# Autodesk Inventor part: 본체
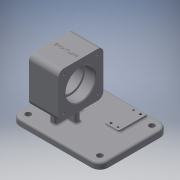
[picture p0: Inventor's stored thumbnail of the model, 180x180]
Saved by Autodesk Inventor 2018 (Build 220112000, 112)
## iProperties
Created: 2019-09
Part Number: 본체
Material: 알루미늄 6061
Document SubType Name: Modeling
Designer: mduedu
Density: 2.71 g/cm^3
Appearance: 기본값
Mass: 636.364 g
Surface Area: 520.125 cm^2
Volume: 234.821 cm^3
Author: mduedu
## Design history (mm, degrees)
sketch "스케치1"
  geometry: L1 (42, -62)-(-84, -62); L2 (-84, -62)-(-84, 36); L3 (-84, 36)-(42, 36); L4 (42, 36)-(42, -62); 1 further point
  constraints: 8 end point, 2 parallel, 1 horizontal, 1 perpendicular
  dimensions: "d0" = 36 distance from line of L3 point (0, 0); "d1" = 98 distance of L1.end L2.end; "d2" = 42 distance from line of L4 point (0, 0); "d3" = 126 distance of L2.end L3.end
extrude "돌출1" new body sketch "스케치1" distance "d4" = 9; taper "d5" = 0 deg
sketch "스케치2"
  geometry: L1 (0, -62)-(0, 36) reference; L2 (27, -32)-(91, -32); L3 (91, -32)-(91, 32); L4 (91, 32)-(27, 32); L5 (27, 32)-(27, -32); L6 (27, -32)-(91, 32); L7 (91, -32)-(27, 32); 3 further points
  constraints: 12 end point, 3 midpoint, 2 parallel, 1 horizontal, 1 horizontal alignment, 1 perpendicular
  dimensions: "d87" = 64 distance of L4.end L3.end; "d88" = 64 distance of L3.end L2.end; "d89" = 59 distance from line of point (59, 0) L1
extrude "돌출2" join sketch "스케치2" stored distance "d8" = 42; taper "d9" = 0 deg
sketch "스케치3"
  geometry: L1 (-17, 4)-(17, 4); L2 (17, 4)-(17, -4); L3 (17, -4)-(-17, -4); L4 (-17, -4)-(-17, 4); L5 (-4, 20)-(4, 20); L6 (4, 20)-(4, -20); L7 (4, -20)-(-4, -20); L8 (-4, -20)-(-4, 20); 5 further points
  constraints: 16 end point, 4 midpoint, 4 parallel, 2 horizontal, 2 horizontal alignment, 2 perpendicular, 2 vertical alignment
  dimensions: "d10" = 8 distance of L5.start L5.end; "d12" = 8 distance of L1.end L2.end; "d13" = 34 distance of L2.end L3.end; "d14" = 40 distance of L5.end L6.end
extrude "돌출3" join sketch "스케치3" stored distance "d15" = 42; taper "d16" = 0 deg
sketch "스케치4"
  geometry: L1 (-32, 91)-(-32, 27) reference; L2 (32, 91)-(-32, 91) reference; L3 (32, 27)-(32, 91) reference; L4 (-32, 27)-(32, 27) reference; C1 r 21 at (0, 59); 3 further points
  constraints: 2 midpoint, 1 centre point, 1 horizontal alignment, 1 vertical alignment
  dimensions: "d17" = 42 diameter of C1
extrude "돌출4" cut sketch "스케치4" distance "d18" = 15; taper "d19" = 0 deg
hole "구멍1" diameter "d22" = 36; stored, may be unused: countersink angle "d26" = 90 deg, drill point angle "d28" = 118 deg; dims "d20" = 10, "d21" = 10, "d23" = 6, "d24" = 4, "d25" = 2, "d27" = 8
fillet "모깎기1" dims "d29" = 0.3
chamfer "모따기1" distance "d30" = 1; stored, may be unused: second distance "d31" = 2, angle "d32" = 45 deg
fillet "모깎기9" dims "d90" = 8
sketch "스케치11"
  geometry: L1 (-24, 27)-(24, 27) reference; L2 (32, 35)-(32, 83) reference; L3 (24, 91)-(-24, 91) reference; L4 (-32, 83)-(-32, 35) reference; C1 r 22 at (0, 59) reference; A1 r 8 centre (-24, 35) between (-32, 35) and (-24, 27) reference; A2 r 8 centre (24, 35) between (24, 27) and (32, 35) reference; A3 r 8 centre (24, 83) between (32, 83) and (24, 91) reference; A4 r 8 centre (-24, 83) between (-24, 91) and (-32, 83) reference; 5 further points
  constraints: 4 coincident
hole "구멍6" sketch "스케치11" at (-24, 83), (24, 83), (24, 35), (-24, 35) diameter "d91" = 3.242; stored, may be unused: countersink angle "d95" = 90 deg, drill point angle "d97" = 118 deg; dims "d92" = 8, "d93" = 4, "d94" = 2, "d96" = 10
fillet "모깎기2" dims "d44" = 12
sketch "스케치6"
  geometry: L1 (-42, 50)-(-42, -24) reference; L2 (-30, -36)-(72, -36) reference; L3 (84, -24)-(84, 50) reference; L4 (72, 62)-(-30, 62) reference; L5 (17, 4)-(17, -4) reference; L6 (17, -4)-(4, -4) reference; L7 (4, -4)-(4, -20) reference; L8 (4, -20)-(-4, -20) reference; L9 (-4, -20)-(-4, -4) reference; L10 (-4, -4)-(-17, -4) reference; L11 (-17, -4)-(-17, 4) reference; L12 (-17, 4)-(-4, 4) reference; L13 (-4, 4)-(-4, 20) reference; L14 (-4, 20)-(4, 20) reference; L15 (4, 20)-(4, 4) reference; L16 (4, 4)-(17, 4) reference; A1 r 12 centre (-30, 50) between (-30, 62) and (-42, 50) reference; A2 r 12 centre (-30, -24) between (-42, -24) and (-30, -36) reference; A3 r 12 centre (72, -24) between (72, -36) and (84, -24) reference; A4 r 12 centre (72, 50) between (84, 50) and (72, 62) reference; 5 further points
  constraints: 4 coincident
hole "구멍3" sketch "스케치6" at (-30, 50), (72, 50), (72, -24), (-30, -24) diameter "d45" = 8; stored, may be unused: countersink angle "d49" = 90 deg, drill point angle "d51" = 118 deg; dims "d46" = 8, "d47" = 4, "d48" = 2, "d50" = 10
sketch "스케치7"
  geometry: L1 (38, 57)-(58, 57); L2 (58, 57)-(58, 17); L3 (58, 17)-(38, 17); L4 (38, 17)-(38, 57); L5 (72, 62)-(-30, 62) reference; 3 further points
  constraints: 8 end point, 2 midpoint, 2 parallel, 1 horizontal, 1 perpendicular
  dimensions: "d52" = 48 horizontal distance of point (48, 57) point (0, 0); "d53" = 20 distance of L1.start L1.end; "d54" = 40 distance of L1.end L2.end; "d55" = 25 distance from line of point (38, 37) L5
extrude "돌출5" join sketch "스케치7" distance "d56" = 3; taper "d57" = 0 deg
fillet "모깎기3" dims "d58" = 3
fillet "모깎기4" dims "d59" = 3
fillet "모깎기5" dims "d60" = 3
fillet "모깎기6" dims "d61" = 3
fillet "모깎기7" dims "d62" = 3
fillet "모깎기8" dims "d63" = 3
sketch "스케치8"
  geometry: L1 (72, 62)-(58.317, 62) reference; L2 (84, -24)-(84, 50) reference; C1 r 1.5 at (43, 53); C2 r 1.5 at (53, 21); 1 further point
  constraints: 2 centre point, 1 equal radius
  dimensions: "d64" = 3 diameter of C1; "d65" = 9 distance from line of C1.centre L1; "d66" = 32 vertical distance of C2.centre C1.centre; "d67" = 10 horizontal distance of C2.centre C1.centre; "d68" = 31 distance from line of L2 C2.centre
hole "구멍4" sketch "스케치8" at (43, 53), (53, 21) diameter "d69" = 3; stored, may be unused: countersink angle "d73" = 90 deg, drill point angle "d75" = 118 deg; dims "d70" = 8, "d71" = 4, "d72" = 2, "d74" = 6
sketch "스케치9"
  geometry: C1 r 1.5 at (43, 53) reference; C2 r 1.5 at (53, 21) reference; 3 further points
  constraints: 2 horizontal alignment, 2 vertical alignment
hole "구멍5" sketch "스케치9" at (53, 53), (43, 21) diameter "d76" = 3.242; stored, may be unused: countersink angle "d80" = 90 deg, drill point angle "d82" = 118 deg; dims "d77" = 6, "d78" = 4, "d79" = 2, "d81" = 8
sketch "스케치10"
  geometry: 2 further points
  constraints: 1 coincident, 1 other
feature "엠보싱1" sketch "스케치10" dims "d0" = 36, "d1" = 98, "d2" = 42, "d3" = 126, "d12" = 8, "d13" = 34, "d85" = 0.5, "d86" = 0
node "솔리드1"
mirror "대칭1"
mirror "대칭2"
node "투영된 루프1"
node "투영된 루프2"
